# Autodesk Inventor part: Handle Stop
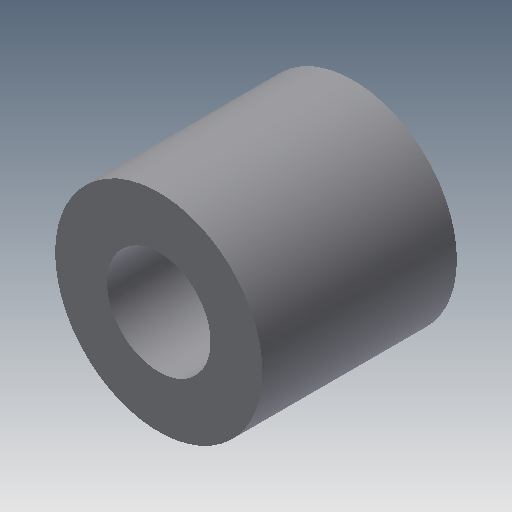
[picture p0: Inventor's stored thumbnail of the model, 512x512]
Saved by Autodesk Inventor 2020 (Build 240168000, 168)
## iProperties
Created: 2002-02
Part Number: Handle Stop
Document SubType Name: Modeling
Designer: ***
Density: 1 g/cm^3
Material: Generic
Mass: 2.36248 g
Surface Area: 14.8283 cm^2
Volume: 2.36248 cm^3
Appearance: Default
Control State: 0
Master: False
Checked Out: False
Shininess: 77.0
Length Units: 11269
Angle Units: 11279
Time Units: 11290
Mass Units: 11283
Length Display Precision: 3
Angle Display Precision: 2
Compacted: True
Density: 0.0
Volumn: 0.0
Area: 0.0
PropertySet Name: Model Information
Author: ***
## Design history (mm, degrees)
sketch "Sketch1"
  geometry: L1 (0, 0)-(0, -2); L2 (0, -2)-(8, -2); L3 (8, -2)-(8, 13); L4 (8, 13)-(4, 13); L5 (4, 13)-(4, 0); L6 (4, 0)-(0, 0)
  constraints: 12 end point, 4 parallel, 1 perpendicular, 1 vertical
  dimensions: "d0" = 16 diameter of L3 L1; "d1" = 8 diameter of L5 L1; "d2" = 2 distance of L1.start L1.end; "d3" = 15 distance of L2.end L3.end
revolve "Revolution1" sketch "Sketch1" stored, may be unused: angle "d4" = 90 deg
body "Solid1"
